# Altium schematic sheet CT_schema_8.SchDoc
size 274 x 160 mm
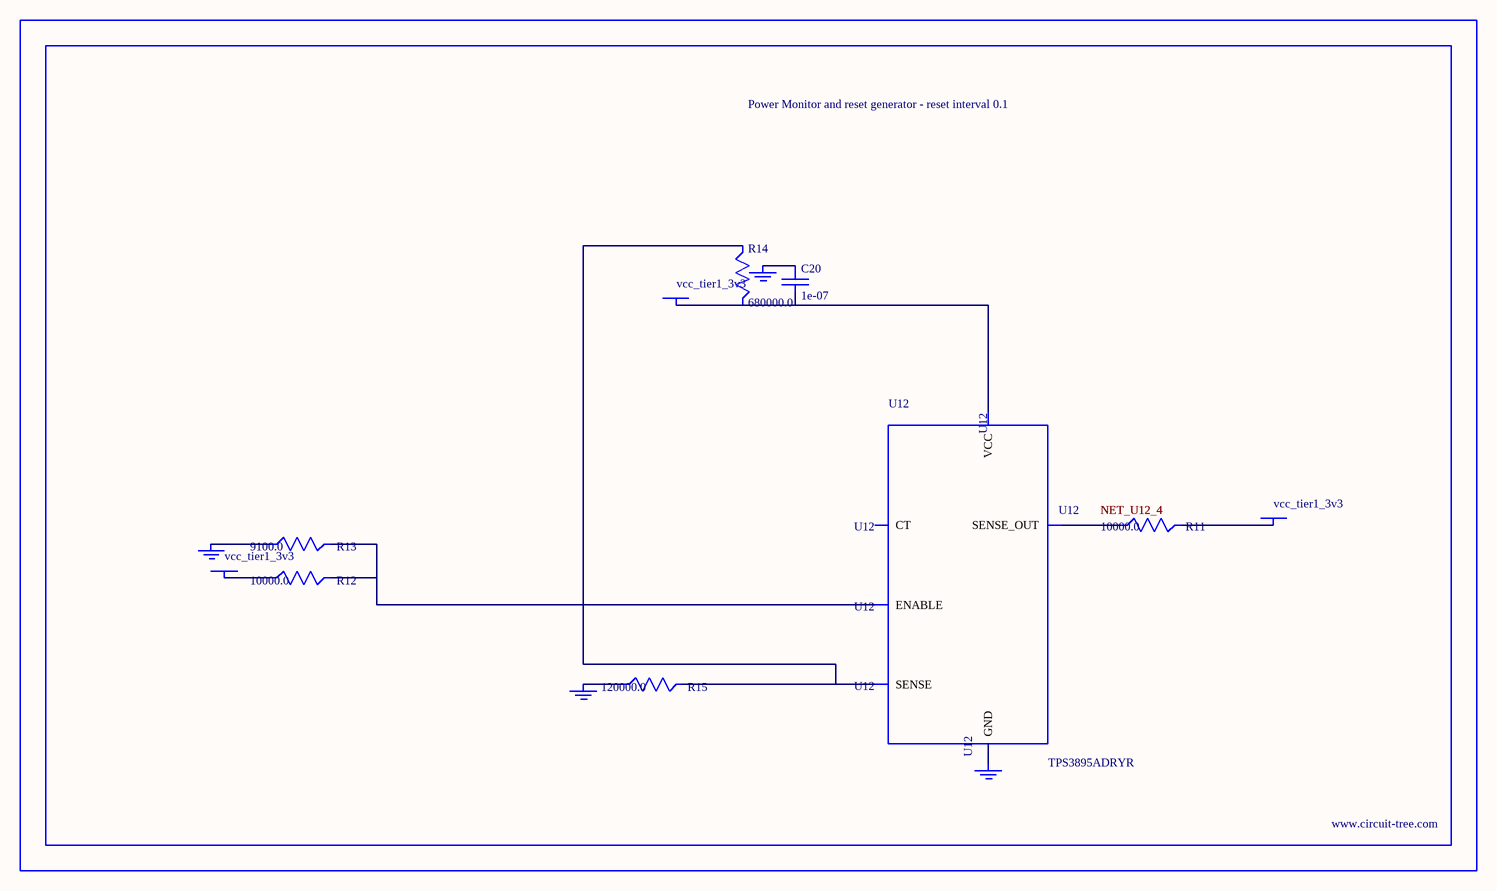
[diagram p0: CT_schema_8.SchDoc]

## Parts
BORDER7  (no value)
C20  1e-07  [C0402]
GND_INSTANCE_7_0  (no value)
GND_INSTANCE_7_1  (no value)
GND_INSTANCE_7_2  (no value)
GND_INSTANCE_7_3  (no value)
POWER_INSTANCE_7_0  vcc_tier1_3v3
POWER_INSTANCE_7_1  vcc_tier1_3v3
POWER_INSTANCE_7_2  vcc_tier1_3v3
R11  10000.0  [R0603]
R12  10000.0  [R0603]
R13  9100.0  [R0603]
R14  680000.0  [R0603]
R15  120000.0  [R0603]
U12  TPS3895ADRYR  [SON-6]

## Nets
NetC20_1: C20.1 GND_INSTANCE_7_2.0(GND)
NetC20_2: C20.2 POWER_INSTANCE_7_2.0(PWR) R14.2 U12.6(VCC)
NetGND_INSTANCE_7_0_0: GND_INSTANCE_7_0.0(GND) R13.1
NetGND_INSTANCE_7_1_0: GND_INSTANCE_7_1.0(GND) R15.1
NetGND_INSTANCE_7_3_0: GND_INSTANCE_7_3.0(GND) U12.2(GND)
NetPOWER_INSTANCE_7_0_0: POWER_INSTANCE_7_0.0(PWR) R12.1
NetPOWER_INSTANCE_7_1_0: POWER_INSTANCE_7_1.0(PWR) R11.2
NetR11_1: R11.1 U12.4(SENSE_OUT)
NetR12_2: R12.2 R13.2 U12.1(ENABLE)
NetR14_1: R14.1 R15.2 U12.3(SENSE)

Not connected (* = marked no-connect by the designer): U12 5(CT)

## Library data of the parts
BORDER7 = BORDER_PAGE7
C20 = C0402C104K3RACTU
GND_INSTANCE_7_0-GND_INSTANCE_7_3 = GND
POWER_INSTANCE_7_0-POWER_INSTANCE_7_2 = PWR
R11 R12 = RC0603JR-0710KL
R13 = RC0603JR-079K1L
R14 = RC0603JR-07680KL
R15 = RC0603JR-07120KL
